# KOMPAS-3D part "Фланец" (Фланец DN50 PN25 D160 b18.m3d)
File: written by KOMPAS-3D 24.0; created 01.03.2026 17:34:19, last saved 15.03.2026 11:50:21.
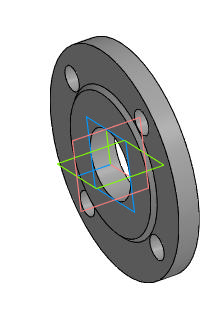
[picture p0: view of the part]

Document properties: Автор: R2D2; Полное имя файла: E:\Работа\Зайцев\GVWR2434M-2W-F-ОСТ Задвижка клиновая с выдвижным штоком DN.ru Ду50-300 Ру25\исходные материалы\DN50\Фланец DN50 PN25 D160 b18.m3d

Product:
- Part/product: Фланец
    Масса: 2.168144
    additional columns: Типовые
- Part/product: Фланец  | designation 01
    Масса: 2.041312
    additional columns: Типовые

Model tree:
1. Эскиз:2
2. Элемент вращения:1
     Угол 1 = 360
3. Эскиз:3  (with: Грань.Элемент вращения:1)
4. Элемент выдавливания:2
     Расстояние 2 = 15
5. Массив по концентрической сетке:1  (with: Элемент выдавливания:2, Эскиз:3, Грань.Элемент вращения:1)  (4 pattern instances)
     Шаг 2 = 360

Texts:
  Линейный размер с обрывом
